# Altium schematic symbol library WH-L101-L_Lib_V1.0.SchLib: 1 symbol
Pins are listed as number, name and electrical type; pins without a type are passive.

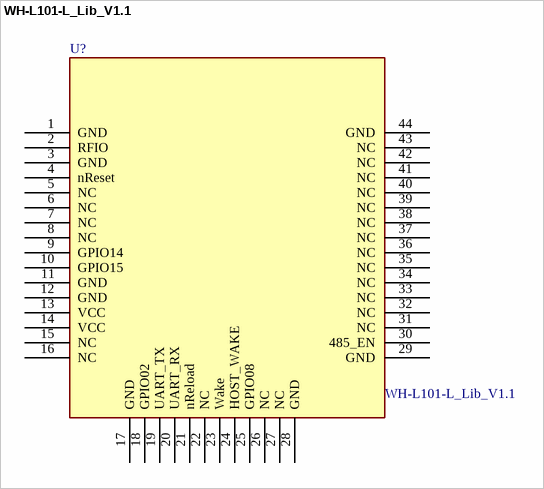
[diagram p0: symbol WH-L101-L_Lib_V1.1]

## WH-L101-L_Lib_V1.1
designator U?
footprint WH-L101-SMT-V1.0 (Footprint not found)
pins: 1 GND, 2 RFIO, 3 GND, 4 nReset, 5 NC, 6 NC, 7 NC, 8 NC, 9 GPIO14, 10 GPIO15, 11 GND, 12 GND, 13 VCC, 14 VCC, 15 NC, 16 NC, 17 GND, 18 GPIO02, 19 UART_TX, 20 UART_RX, 21 nReload, 22 NC, 23 Wake, 24 HOST_WAKE, 25 GPIO08, 26 NC, 27 NC, 28 GND, 29 GND, 30 485_EN, 31 NC, 32 NC, 33 NC, 34 NC, 35 NC, 36 NC, 37 NC, 38 NC, 39 NC, 40 NC, 41 NC, 42 NC, 43 NC, 44 GND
